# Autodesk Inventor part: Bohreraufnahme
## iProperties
Created: 2007-04
Part Number: Bohreraufnahme
Document SubType Name: Modeling
Designer: Benno
Manufacturer: Standard
Standards Organization: Custom
Author: Benno
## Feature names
1. Extrusion1
2. Extrusion2
3. Extrusion3
4. Rundung1 [Fillet]
5. Fase1 [Chamfer]
6. Rundung2 [Fillet]
7. Bohrung1 [Hole]
8. Bohrung2 [Hole]
9. Bohrung3 [Hole]
10. Bohrung4 [Hole]
11. Bohrung5 [Hole]
12. Bohrung6 [Hole]
13. Bohrung7 [Hole]
14. Bohrung8 [Hole]
15. Bohrung9 [Hole]
16. Rundung3 [Fillet]
